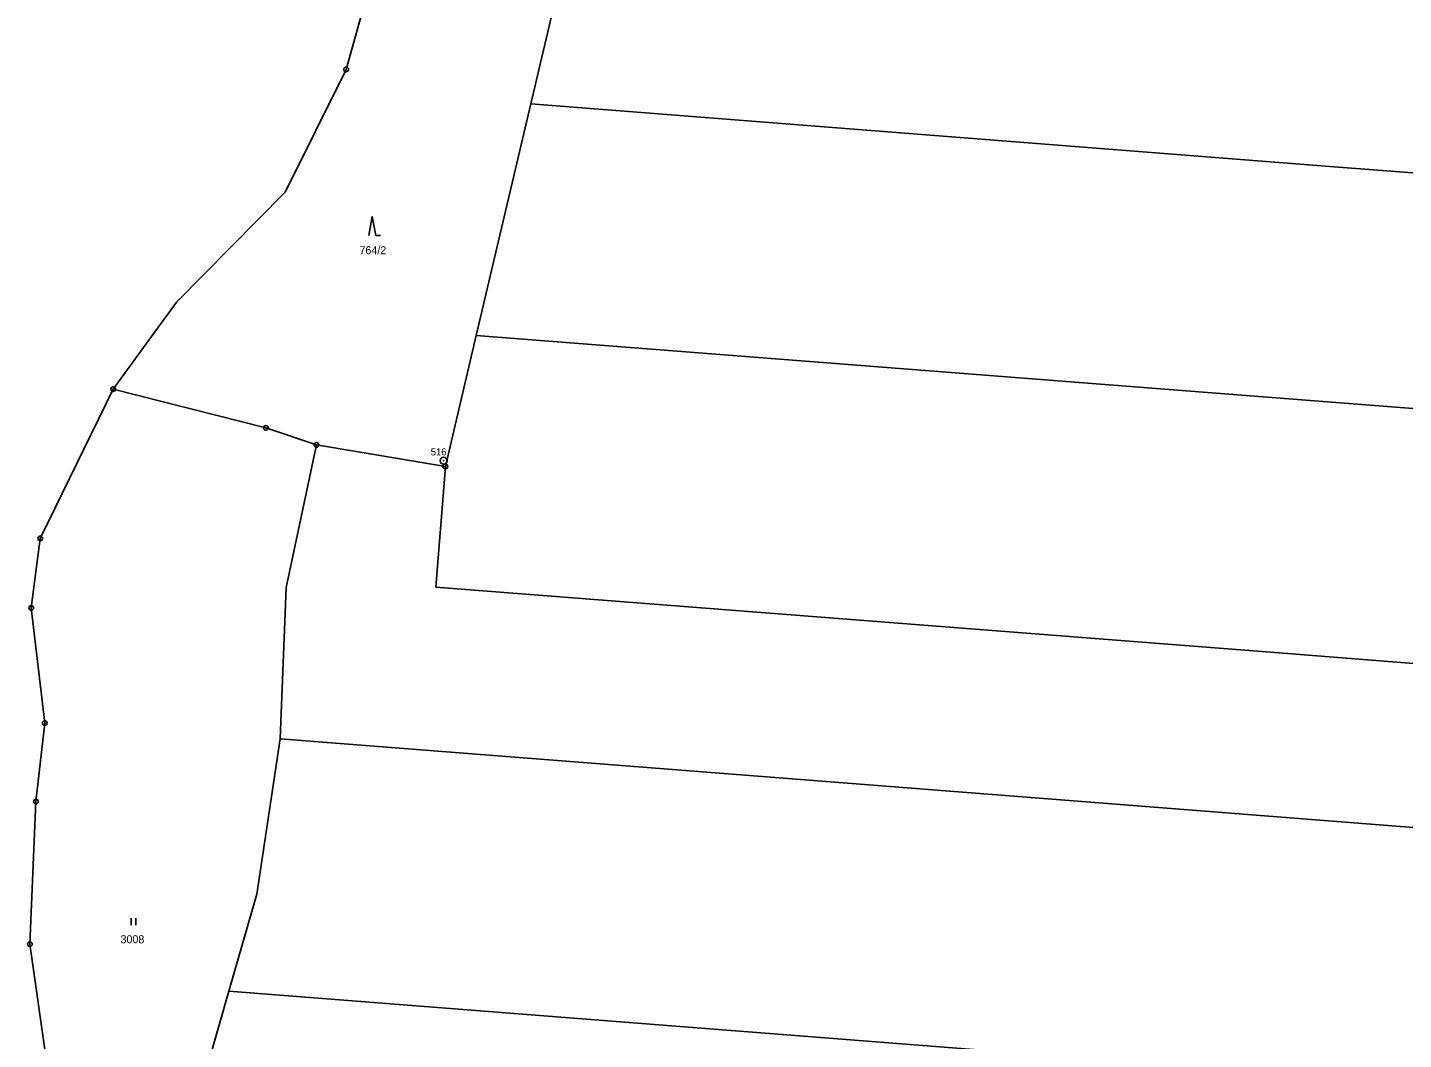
# Model space of a CAD drawing. Extents: x -618848 to -615803, y -1044450 to -1042254.
# Drawn here: x -618573.4 to -618281.1, y -1042997.1 to -1042782 of the extents above; entities that cross this region are included whole.
import ezdxf
from ezdxf.enums import TextEntityAlignment as Align

# ---------------------------------------------------------------- set-up
doc = ezdxf.new("R2010")
doc.units = 0
doc.header["$LTSCALE"] = 0.68
for name, color, linetype, lineweight in [('1', 7, 'Continuous', 25), ('3', 7, 'Continuous', 25), ('8', 7, 'Continuous', 25)]:
    doc.layers.add(name, color=color, linetype=linetype, lineweight=lineweight)
doc.layers.add('2', color=7, linetype='Continuous')

msp = doc.modelspace()

# ---------------------------------------------------------------- linework, layer by layer
at = {"layer": '1'}
for p, q in [((-618500.78, -1042772.99), (-618505.75, -1042790.9)), ((-618461.51, -1042776.92), (-618466.53, -1042798.25)), ((-618505.75, -1042790.9), (-618518.73, -1042816.98)), ((-618466.53, -1042798.25), (-618478.11, -1042847.43)), ((-618466.53, -1042798.25), (-618296.74, -1042811.52)), ((-618296.74, -1042811.52), (-618126.95, -1042824.78)), ((-618518.73, -1042816.98), (-618541.78, -1042840.4)), ((-618541.78, -1042840.4), (-618555.24, -1042858.84)), ((-618478.11, -1042847.43), (-618484.68, -1042875.29)), ((-618300.92, -1042861.27), (-618478.11, -1042847.43)), ((-618555.24, -1042858.84), (-618570.74, -1042890.57)), ((-618522.79, -1042867.1), (-618555.24, -1042858.84)), ((-618123.72, -1042875.12), (-618300.92, -1042861.27)), ((-618512.07, -1042870.71), (-618522.79, -1042867.1)), ((-618518.48, -1042900.97), (-618512.07, -1042870.71)), ((-618484.68, -1042875.29), (-618512.07, -1042870.71)), ((-618484.68, -1042875.29), (-618486.67, -1042900.92)), ((-618570.74, -1042890.57), (-618572.66, -1042905.36)), ((-618519.79, -1042933.17), (-618518.48, -1042900.97)), ((-618486.67, -1042900.92), (-618308.45, -1042914.84)), ((-618572.66, -1042905.36), (-618569.8, -1042929.81)), ((-618308.45, -1042914.84), (-618130.22, -1042928.76)), ((-618569.8, -1042929.81), (-618571.68, -1042946.51)), ((-618519.79, -1042933.17), (-618524.73, -1042966.14)), ((-618359.35, -1042945.7), (-618519.79, -1042933.17)), ((-618198.9, -1042958.24), (-618359.35, -1042945.7)), ((-618571.68, -1042946.51), (-618572.95, -1042976.8)), ((-618524.73, -1042966.14), (-618530.67, -1042986.81)), ((-618572.95, -1042976.8), (-618569.13, -1043003.7)), ((-618530.67, -1042986.81), (-618548.9, -1043050.68)), ((-618530.67, -1042986.81), (-618372.36, -1042999.18))]:
    msp.add_line(p, q, dxfattribs=at)
at = {"layer": '3'}
for p, q in [((-618499.46, -1042826.17), (-618498.464, -1042826.17)), ((-618551.461, -1042972.77), (-618551.461, -1042971.27)), ((-618550.46, -1042972.77), (-618550.46, -1042971.27))]:
    msp.add_line(p, q, dxfattribs=at)
msp.add_lwpolyline([(-618499.46, -1042826.17), (-618500.21, -1042822.17), (-618500.96, -1042826.17)], dxfattribs=at)
at = {"layer": '8'}
for centre, radius in [((-618505.75, -1042790.8999), 0.5), ((-618505.75, -1042790.8999), 0.0303), ((-618555.24, -1042858.8399), 0.5), ((-618555.24, -1042858.8399), 0.0303), ((-618522.79, -1042867.0999), 0.5), ((-618522.79, -1042867.0999), 0.0303), ((-618512.07, -1042870.7099), 0.5), ((-618512.07, -1042870.7099), 0.0303), ((-618485.05, -1042874.0598), 0.75), ((-618484.68, -1042875.2899), 0.5), ((-618485.05, -1042874.0598), 0.03), ((-618484.68, -1042875.2899), 0.0303), ((-618570.74, -1042890.5699), 0.5), ((-618570.74, -1042890.5699), 0.0303), ((-618572.66, -1042905.3599), 0.5), ((-618572.66, -1042905.3599), 0.0303), ((-618569.8, -1042929.8099), 0.5), ((-618569.8, -1042929.8099), 0.0303), ((-618571.68, -1042946.5099), 0.5), ((-618571.68, -1042946.5099), 0.0303), ((-618572.95, -1042976.7999), 0.5), ((-618572.95, -1042976.7999), 0.0303)]:
    msp.add_circle(centre, radius, dxfattribs=at)

# ---------------------------------------------------------------- texts
at = {"layer": '2'}
msp.add_text('764/2', height=1.7, dxfattribs=at).set_placement((-618500.08, -1042830.185), align=Align.CENTER)
msp.add_text('3008', height=1.7, dxfattribs=at).set_placement((-618553.69, -1042976.605))
at = {"layer": '8'}
msp.add_text('516', height=1.5, dxfattribs=at).set_placement((-618487.78, -1042872.935))

doc.saveas('drawing.dxf')
